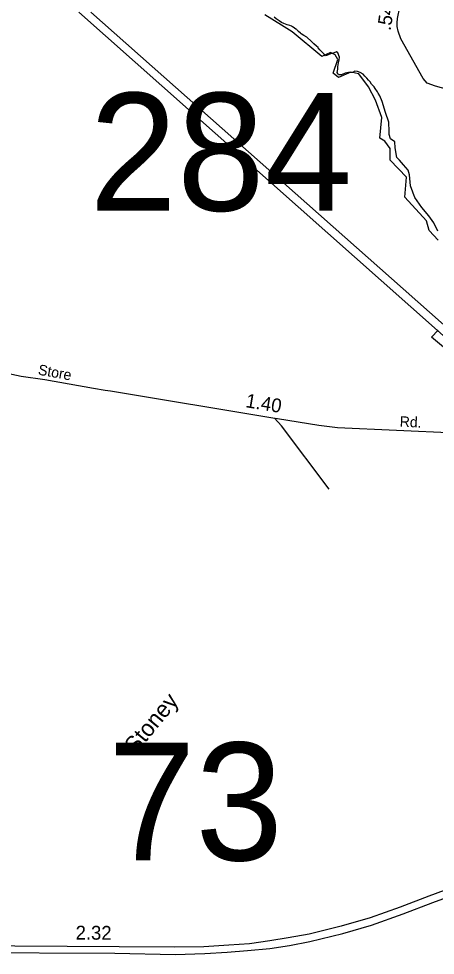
# Model space of a CAD drawing. Extents: x 2220236 to 2384410, y 720751 to 894131.
# Drawn here: x 2319308 to 2323081, y 812157 to 820637 of the extents above; entities that cross this region are included whole.
import ezdxf

# ---------------------------------------------------------------- set-up
doc = ezdxf.new("R2010")
doc.units = 0
doc.layers.add('Default', color=7, linetype='Continuous')

msp = doc.modelspace()

# ---------------------------------------------------------------- linework, layer by layer
at = {"layer": 'Default'}
for points in [[(2323223.5, 819987.8), (2323083.2, 820026.7), (2323008.8, 820053.2), (2322972.4, 820096.2), (2322767.5, 820455.1), (2322745.1, 820524.4), (2322736.9, 820566.7), (2322734.2, 820600.6), (2322739.1, 820640.3), (2322743.3, 820670.4), (2322755.1, 820710.6), (2322777.7, 820752), (2322815.4, 820793.3), (2322820.5, 820797.9)], [(2319853.3, 820695.9), (2326592.3, 814719.1), (2333025.8, 805564.5)], [(2333024.4, 805702.5), (2331824.6, 807406.8), (2329674.8, 810458.2), (2329041.4, 811359.1), (2328249.6, 812486.1), (2327790.8, 813138.8), (2326970.6, 814303.4), (2326633.7, 814783.6), (2326625.6, 814795.5), (2319961.3, 820697.1)], [(2323106.5, 818630.9), (2323024.1, 818718.8), (2323002.1, 818806.8), (2322804.4, 819021.2), (2322820.9, 819202.6), (2322672.5, 819356.5), (2322672.5, 819460.9), (2322623.1, 819526.9), (2322579.2, 819554.4), (2322595.6, 819741.3), (2322540.7, 819900.7), (2322474.8, 820021.6), (2322386.9, 820137.1), (2322315.5, 820153.6), (2322205.6, 820104.1), (2322156.2, 820142.6), (2322197.4, 820266.3), (2322175.4, 820310.2), (2322131.5, 820332.2), (2322054.6, 820293.7), (2321785.4, 820519.1), (2321686.5, 820579.6), (2321538.2, 820673)], [(2323105, 818713.9), (2323068.2, 818789.6), (2323022.8, 818853.6), (2322957.8, 818928.4), (2322894.8, 819018.9), (2322886.8, 819041), (2322880.8, 819057.6), (2322878, 819065.2), (2322856.5, 819124.5), (2322846.2, 819223.4), (2322834.2, 819264.6), (2322793.2, 819313), (2322755.8, 819355.6), (2322733.2, 819381), (2322717.8, 819469.1), (2322715.5, 819522.7), (2322674.8, 819549.5), (2322662.8, 819589.6), (2322662, 819616.9), (2322659.8, 819700.8), (2322631, 819786.8), (2322600, 819887.7), (2322579.2, 819938.6), (2322564, 819962.3), (2322556.8, 819975.4), (2322537.8, 820004.2), (2322526.2, 820020.6), (2322516, 820032), (2322503.8, 820043.6), (2322490, 820066), (2322476, 820079.2), (2322474.8, 820080.3), (2322461.5, 820098.6), (2322444, 820117.4), (2322426.8, 820135.3), (2322401.2, 820149.6), (2322374.8, 820160.2), (2322350.8, 820162.5), (2322329.5, 820150.8), (2322296.2, 820150.1), (2322265.2, 820143.1), (2322230, 820129.4), (2322204.8, 820130.4), (2322199.5, 820139.5), (2322193.5, 820149.6), (2322193.8, 820164.4), (2322197.8, 820181.7), (2322197.8, 820201.3), (2322204.2, 820238.5), (2322211, 820266.2), (2322213.2, 820289.9), (2322198, 820327.8), (2322185, 820337.8), (2322166.2, 820328.4), (2322132, 820319.4), (2322104, 820307.7), (2322086, 820299.9), (2322073.5, 820316.2), (2322053.5, 820337), (2322035.2, 820355.8), (2322021.2, 820372.4), (2322018.8, 820375.1), (2322005.2, 820389.2), (2321979.5, 820409.9), (2321959.5, 820431), (2321916.5, 820471.2), (2321891.5, 820485.4), (2321865.5, 820500.9), (2321861.2, 820504.8), (2321841.8, 820522.4), (2321829.8, 820534.8), (2321825.8, 820537.9), (2321818, 820543.9), (2321792.5, 820561.8), (2321789, 820563.8), (2321778.2, 820570.1), (2321763.2, 820574.8), (2321738.2, 820582.7), (2321709, 820594.5), (2321687, 820603.2), (2321666.2, 820618.3), (2321640.8, 820635.8), (2321622.8, 820651.2)], [(2323105, 818713.9), (2323068.2, 818789.6), (2323022.8, 818853.6), (2322957.8, 818928.4), (2322894.8, 819018.9), (2322886.8, 819041), (2322880.8, 819057.6), (2322878, 819065.2), (2322856.5, 819124.5), (2322846.2, 819223.4), (2322834.2, 819264.6), (2322793.2, 819313), (2322755.8, 819355.6), (2322733.2, 819381), (2322717.8, 819469.1), (2322715.5, 819522.7), (2322674.8, 819549.5), (2322662.8, 819589.6), (2322662, 819616.9), (2322659.8, 819700.8), (2322631, 819786.8), (2322600, 819887.7), (2322579.2, 819938.6), (2322564, 819962.3), (2322556.8, 819975.4), (2322537.8, 820004.2), (2322526.2, 820020.6), (2322516, 820032), (2322503.8, 820043.6), (2322490, 820066), (2322476, 820079.2), (2322474.8, 820080.3), (2322461.5, 820098.6), (2322444, 820117.4), (2322426.8, 820135.3), (2322401.2, 820149.6), (2322374.8, 820160.2), (2322350.8, 820162.5), (2322329.5, 820150.8), (2322296.2, 820150.1), (2322265.2, 820143.1), (2322230, 820129.4), (2322204.8, 820130.4), (2322199.5, 820139.5), (2322193.5, 820149.6), (2322193.8, 820164.4), (2322197.8, 820181.7), (2322197.8, 820201.3), (2322204.2, 820238.5), (2322211, 820266.2), (2322213.2, 820289.9), (2322198, 820327.8), (2322185, 820337.8), (2322166.2, 820328.4), (2322132, 820319.4), (2322104, 820307.7), (2322086, 820299.9), (2322073.5, 820316.2), (2322053.5, 820337), (2322035.2, 820355.8), (2322021.2, 820372.4), (2322018.8, 820375.1), (2322005.2, 820389.2), (2321979.5, 820409.9), (2321959.5, 820431), (2321916.5, 820471.2), (2321891.5, 820485.4), (2321865.5, 820500.9), (2321861.2, 820504.8), (2321841.8, 820522.4), (2321829.8, 820534.8), (2321825.8, 820537.9), (2321818, 820543.9), (2321792.5, 820561.8), (2321789, 820563.8), (2321778.2, 820570.1), (2321763.2, 820574.8), (2321738.2, 820582.7), (2321709, 820594.5), (2321687, 820603.2), (2321666.2, 820618.3), (2321640.8, 820635.8), (2321622.8, 820651.2)], [(2323210.9, 817617.8), (2323046.1, 817755.2), (2323106.5, 817815.7)], [(2319202.7, 817426.4), (2319331, 817401.7), (2319545.1, 817370), (2319985.7, 817290.8), (2320092, 817273.9), (2320138.1, 817268.6), (2321608, 817022.5), (2321650.5, 817017.1), (2322027.5, 816957.9), (2322194.5, 816934.9), (2323264.6, 816888.3), (2323342.6, 816889.1), (2323981.9, 816857.7)], [(2322118.6, 816378.2), (2321686.7, 816951.3), (2321623.2, 817019.9)], [(2325096.7, 813467), (2324935.5, 813408.1), (2324688.4, 813317.1), (2324367.9, 813196.7), (2323875.6, 813007.5), (2323625.9, 812915.5), (2323023.3, 812691.9), (2322762.5, 812591.8), (2322489.6, 812495.7), (2322228.7, 812420.8), (2321938.6, 812348), (2321749.6, 812315.7), (2321581.7, 812288.3), (2321397.3, 812261.7), (2321209.7, 812247.9), (2320983.3, 812234.7), (2320718.4, 812230.7), (2320218, 812234.7), (2318799.7, 812243.8)], [(2318806.7, 812181.1), (2320179.6, 812177.1), (2320725.5, 812162.9), (2320992.4, 812173), (2321195.6, 812184.2), (2321379.6, 812200.3), (2321581.7, 812218.5), (2321760.7, 812244.8), (2321943.7, 812281.3), (2322242.9, 812353.1), (2322503.7, 812430), (2322788.8, 812531.1), (2323060, 812635.1), (2323652.5, 812851.1), (2323900.8, 812943.8), (2324381, 813129.9), (2324723.2, 813253.3), (2324943.6, 813334.3), (2325087.8, 813389.2)]]:
    msp.add_lwpolyline(points, dxfattribs=at)

# ---------------------------------------------------------------- texts
for s, height, rotation, p in [('.54', 125, 81.50237, (2322676.1, 820524.8)), ('Store', 95, 349.80963, (2319477.7, 817415.4)), ('1.40', 125, 350.49536, (2321356.6, 817120.7)), ('Rd.', 95, 357.50661, (2322757.3, 816943.2)), ('Stoney', 150, 50.57425, (2320366.5, 813972.1)), ('2.32', 125, 359.63229, (2319822.9, 812299.8))]:
    msp.add_text(s, height=height, rotation=rotation, dxfattribs=at).set_placement(p)
for s, p in [('284', (2319948.7, 818898.8)), ('73', (2320115.5, 813016.8))]:
    msp.add_text(s, height=1066.27, dxfattribs=at).set_placement(p)

doc.saveas('drawing.dxf')
